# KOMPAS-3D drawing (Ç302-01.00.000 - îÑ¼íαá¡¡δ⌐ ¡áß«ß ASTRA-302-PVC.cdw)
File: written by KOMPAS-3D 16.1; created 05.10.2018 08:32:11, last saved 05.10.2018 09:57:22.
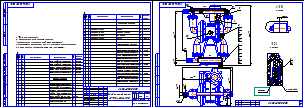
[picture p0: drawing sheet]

Sheets 1-2: A3, landscape

Title block, sheet 1: name: Мембранный насос / ASTRA-302-PVC; designation: А302-01.00.000; mass: 52,5; scale: 1:5; sheet number: 1; sheets: 2; organisation: ЗАО «Астерион»; sheet format: A3; stored path: \\192.168.87.28\Konstructor_doc\Мембранные насосы\Мембранный электропривод\А302-00.00.000 - ASTRA-302 (МЭ200)\3Д ПВХ\А302-01.00.000 - Мембранный насос ASTRA-302-PVC.cdw; drawn by: Милов; technical control: Лучихин
Title block, sheet 2: sheet number: 2

Views: Выносной элемент 3, Выносной элемент А, Выносной элемент, Вид:1
Referenced files in Z:\Мембранные насосы\Мембранный электропривод\А302-00.00.000 - ASTRA-302 (МЭ200)\3Д ПВХ\: А302-01.00.000  - Мембранный насос ASTRA-302 ПВХ.a3d, А302-01.15.001 - Мембрана.m3d, А302-01.15.003 - Шайба.m3d, А302-01.15.002 - Упор.m3d, А302-01.15.008 - Кольцо плоское Ф4.m3d, А302-01.15.009 - Кольцо плоское Ф4.m3d, А302-01.15.001-01- Мембрана.m3d, А302-01.15.007 - Заглушка.m3d, А302-01.15.011 - Заглушка резьбовая.m3d, А302-01.15.000 - Мембрана.a3d, А302-01.11.000 - Крышка рабочей камеры.a3d, А302-01.10.001 - Седло.m3d, А302-01.10.002 3Д - Стакан.m3d, А302-01.10.000 - Рабочая камера.a3d
Referenced files in \\192.168.87.28\Konstructor_doc\Мембранные насосы\Мембранный электропривод\А302-00.00.000 - ASTRA-302 (МЭ200)\3Д ПВХ\: А302-01.05.000 - Корпус.cdw, А302-01.15.000 - Мембрана.cdw, А302-01.10.000 - Рабочая камера.cdw, А302-01.40.000 - Каркас.cdw, А302-01.20.001 - Основание.m3d, А302-01.35.000 - Фланец.a3d, А302-01.20.002 - Эксцентрик.m3d, А302-01.05.001 - Основание.m3d, А302-01.05.012 - Фиксатор.m3d, А302-01.05.011 - Ловитель.m3d, А302-01.05.015 - Фиксатор.m3d, А302-01.12.001 - Крышка.m3d, А302-01.12.000 - Крышка.a3d, А302-01.31.001 - Корпус.m3d, А302-01.31.000 - Корпус.a3d, А302-01.30.001 - Прижим.m3d, А302-01.30.000 - Прижим.a3d, А302-01.40.000 - Каркас.a3d
Referenced files: graphic.tdp
Referenced files in \\192.168.87.28\Konstructor_doc\1 ПКИ 3D\Двигатели\АИР\: Электродвигатель АИР 80А4 IM 3081 1,1кВт 1400 об..m3d
Referenced files in \\192.168.87.28\Konstructor_doc\1 ПКИ 3D\Редуктора NMRW\Редукторы\: Редуктор NMRW 063.m3d, Червячный мотор-редуктор NMRV063 АИР80.a3d
Referenced files in \\192.168.87.28\Konstructor_doc\Мембранные насосы\Мембранный электропривод\А302-00.00.000 - ASTRA-302 (МЭ200)\3Д\: А302-00.35.002 - Пластина.m3d, А302-00.35.001 - Труба 140х140х4.m3d, А302-00.20.004 - Вал.m3d, А302-00.20.003 - Ползун.m3d
Referenced files in C:\Program Files\ASCON\KOMPAS-3D V16\Libs\PartLib\DATA\vault\Methods\Kompas\3D\: PLib_Check_spring_rings_GOST_13942_911.m3d, PLib_Washer_1_712.m3d, PLib_Washer_2_712.m3d, PLib_Nut_OST92_900.m3d, PLib_Screw_DIN_7984_1500.m3d, PLib_Key_prismatic_712.m3d, PLib_Screw_ISO_10642_1500.m3d, PLib_Bolt_1_ISO_1100.m3d, PLib_Nut_ISO_1100.m3d
Referenced files in \\192.168.87.28\Konstructor_doc\1 ПКИ 3D\1 Крепеж стандартный\Подшипник\: Подшипник 52х25х15 62052RSH SKF.m3d, Подшипник 80х40х18 6208-2RS1 SKF.m3d
Referenced files in C:\Program Files\ASCON\KOMPAS-3D V16\Libs\PartLib\DATA\VAULT\Methods\kompas\3d\: PLib_Bolt_1_900.m3d
Referenced files in \\192.168.87.28\Konstructor_doc\Мембранные насосы\Мембранный электропривод\А302-00.00.000 - ASTRA-302 (МЭ200)\3Д ПВХ\Отработка\: А302-01.20.000 - Мотор-редуктор.a3d, А302-01.05.002 - Ловитель.m3d, Упор-1.m3d, А302-01.05.000 - Корпус.a3d, Труба ПВХ PN10 50х2,4.m3d, Труба профильная 25х25х1,5.m3d, Труба профильная 25х25х1,5-1.m3d, А302-01.40.002-01 - Стяжка.m3d, Труба профильная 25х25х1,5-2.m3d, Квадратная внутренняя заглушка 140х140 мм.m3d
Referenced files in Z:\2 Стандартные изделия 3D\Гайки\DIN 6927\: Гайка шестигранная самостопорящаяся с фланцем DIN 6927-M5 - A2-70.m3d, Гайка шестигранная самостопорящаяся с фланцем DIN 6927-M6 - A2-70.m3d
Referenced files in Z:\Мембранные насосы\Мембранный электропривод\А302-00.00.000 - ASTRA-302 (МЭ200)\3Д ПВХ\Отработка\: Отвод ПВХ 90гр 50 арт.GIV050.m3d, Отвод ПВХ 45гр 50 арт.HIV050.m3d, Тройник равносторонний ПВХ 90гр 50 арт.TIV050.m3d, Штуцер для шланга 50х52х50 арт.AIV050052050.m3d
Referenced files in Z:\1 ПКИ 3D\2 Китай\: Шар PTFE ф60.m3d
Referenced files in D:\МЭ200\Макеты\: Заготовка стакан.m3d
Referenced files in Z:\1 ПКИ 3D\РТИ\Кольца ГОСТ 9833-76\: Кольцо 072-78-25 EPDM ГОСТ 9833-76.m3d
Referenced files in \\192.168.87.28\Konstructor_doc\1 ПКИ 3D\РТИ\Кольца ГОСТ 9833-76\: Кольцо 072-78-25 EPDM ГОСТ 9833-76.m3d
Referenced files in D:\3Д модели\Крепеж\: Гайка шестигранная самостопорящаяся с фланцем DIN 6927-M6 - A2-70.m3d
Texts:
  *Размеры для справок.
  Разделку кромок выполнить согласно:
  "Инструкция по склеиванию ПВХ труб и фитингов".
  - расположение Konstructor_doc Z:\5 Оснастка и приспособления
  Общие допуски ГОСТ 30893.2-mK (H14, h14,  t2/2).
  Корпус
  @100~)2xA3
  Мембрана
  Шайба C 12.21 ГОСТ 6958-78
  Крепежное изделие ГОСТ
  Шайба
  ГОСТ
  Нерж.
  Сталь 12Х18Н10Т ГОСТ 5632-72
  Рабочая камера
  Шайба C.6.21 ГОСТ 11371-78
  Шайба 6 30Х13 019 ГОСТ 6402-70
  Сталь 30Х13 ГОСТ 5632-72
  Винт с цилиндрической головкой
  и шестигранным углублением под ключ
  ГОСТ Р ИСО  4762-М6 x 50-A2-70
  Винт с цилиндрической головкой и шестигранным углублением под ключ
  Р ИСО
  Нержавеющая сталь
  Гайка шестигранная самостопорящаяся
  с фланцем DIN 6927-M6-A2-70
  Гайка
  шестигранная
  самостопорящаяся
  фланцем
  DIN
  Винт с цилиндрической головкой и шестигранным углублением под ключ ГОСТ Р ИСО  4762-М6 x 50-A2-70
  Отвод ПВХ 90   50 арт.GIV050
  Отвод ПВХ 90@1~ @2~50 арт.GIV050
  Труба ПВХ PN10 50х2,4
  Тройник равносторонний
  ПВХ 90   50 арт.TIV050
  Тройник равносторонний / ПВХ 90@1~ @2~50 арт.TIV050
  Каркас
  Квадратная внутренняя заглушка 140х140 мм
  Винт с потайной головкой и
  шестигранным углублением под ключ
  ГОСТ Р ИСО  10642-М8 x 40-8.8-A3J
  Винт с потайной головкой и шестигранным углублением под ключ
  Сталь
  Шайба C.8.04.019 ГОСТ 11371-78
  Сталь 20 ГОСТ 1050-2013
  Шайба 8 30Х13 019 ГОСТ 6402-70
  Гайка М8-6H.5.019 ГОСТ 5915-70
  ГОСТ Р ИСО  4762-М8 x 40-6.8-A9J
  Штуцер ПВХ для шланга 50х52х50
  арт.AIV050052050
  Штуцер ПВХ для шланга 50х52х50 / арт.AIV050052050
  Лит-Масса-Масштаб
  Материал-Предприятие
  Title Specification
  Body Specification ( left align )
  Body Specificaton ( centered )
  Поз.
  Кол.
  Приме-
  чание
  Таблица спецификации
  Электродвигатель АИР 80А4 IM 3081 1,1кВт 1400 об.
  Редуктор NMRW 063
  Червячный мотор-редуктор NMRV063 АИР80
  Основание
  Пластина
  Труба 140х140х4
  Фланец
  Эксцентрик
  Кольцо A25.65Г ГОСТ 13942-86
  Подшипник 52х25х15 62052RSH SKF
  Вал
  Ползун
  Шайба C.5.04.019 ГОСТ 11371-78
  Болт М5-6gx35.58.019 ГОСТ 7805-70
  Шайба 5 30Х13 019 ГОСТ 6402-70
  Гайка М5-6H.5.019 ГОСТ 5915-70
  Шайба C.8.21 ГОСТ 11371-78
  Винт с цилиндрической головкой и шестигранным углублением под ключ ГОСТ Р ИСО 4762 - М8 x 25 - A2-70
  Винт с цилиндрической головкой и шестигранным углублением под ключ ГОСТ Р ИСО 4762 - М8 x 35 - A2-70
  Гайка М8-6H.21.12Х18Н10Т ГОСТ 5915-70
  Шпонка 8x7x90 ГОСТ 23360-78
  Мотор-редуктор
  Ловитель
  Шайба C 8.04.019 ГОСТ 6958-78
  Болт М8-6gx30.58.019 ГОСТ 7805-70
  Подшипник 80х40х18 6208-2RS1 SKF
  Фиксатор
  Упор
  Шайба C.5.21 ГОСТ 11371-78
  Винт с цилиндрической головкой и шестигранным углублением под ключ ГОСТ Р ИСО 4762 - М5 x 16 - 6.8 - A9J
  Винт с цилиндрической головкой и шестигранным углублением под ключ ГОСТ Р ИСО 4762 - М5 x 12 - 6.8 - A9J
  Винт с потайной головкой и шестигранным углублением под ключ ГОСТ Р ИСО 10642 - М4 x 20 - 8.8 - A3J
  Винт с цилиндрической головкой и шестигранным углублением под ключ ГОСТ Р ИСО 4762 - М8 x 45 - 6.8 - A9J
  Винт с цилиндрической головкой и шестигранным углублением под ключ ГОСТ Р ИСО 4762 - М8 x 35 - 6.8 - A9J
  Кольцо A40.65Г ГОСТ 13942-86
  Болт с шестигранной головкой с фланцем ГОСТ Р 55739 - М5 x 25 - A2-70
  Гайка шестигранная с фланцем ГОСТ Р ИСО 4161 - M5 - A2-70
  Гайка шестигранная самостопорящаяся с фланцем DIN 6927-M5 - A2-70
  Кольцо плоское уплотнительное 5-13-10 Ф4
  Болт с шестигранной головкой с фланцем ГОСТ Р 55739 - М8 x 30 - A2-70
  Кольцо плоское Ф4
  Заглушка
  Заглушка резьбовая
  Крышка
  Отвод ПВХ 90гр 50 арт.GIV050
  Отвод ПВХ 45гр 50 арт.HIV050
  Крышка рабочей камеры
  Седло
  Шар PTFE ф60
  Стакан
  Прижим
  Шайба 6 30Х13 ГОСТ 6402-70
  Гайка шестигранная самостопорящаяся с фланцем DIN 6927-M6 - A2-70
  Винт с цилиндрической головкой и шестигранным углублением под ключ ГОСТ Р ИСО 4762 - М6 x 40 - A2-70
  Кольцо 072-78-25 EPDM ГОСТ 9833-76
  Винт с цилиндрической головкой и шестигранным углублением под ключ ГОСТ Р ИСО 4762 - М6 x 50 - A2-70
  Тройник равносторонний ПВХ 90гр 50 арт.TIV050
  Труба профильная 25х25х1,5
  Опора
  Стяжка
  Винт с потайной головкой и шестигранным углублением под ключ ГОСТ Р ИСО 10642 - М8 x 40 - 8.8 - A3J
  Винт с цилиндрической головкой и шестигранным углублением под ключ ГОСТ Р ИСО 4762 - М8 x 40 - 6.8 - A9J
  Штуцер для шланга 50х52х50 арт.AIV050052050
Dimensions and other numbers on the sheet: 2 места; 1±0,05; 4; 3; 12; 21; 40Х; 019; 2; 13; 10; 58; 30Х13; 7; 5; 17; 19; 50; 18; 15; 6; 8.8; 14; 04; 11; 9; 8; 6.8; 20; 1:5; 52,5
